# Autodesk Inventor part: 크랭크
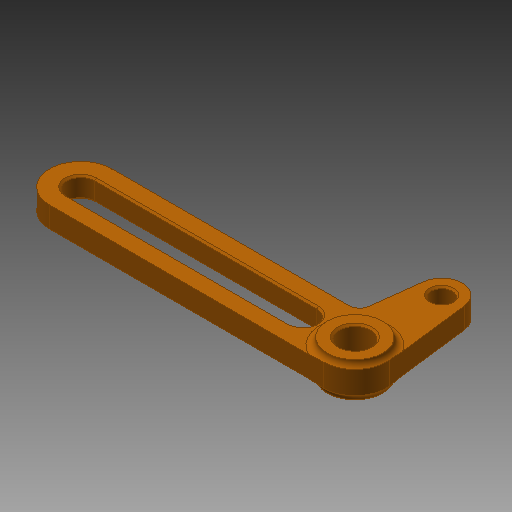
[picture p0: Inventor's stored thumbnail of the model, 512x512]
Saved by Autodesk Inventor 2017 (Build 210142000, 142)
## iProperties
Created: 2019-09
Part Number: 크랭크
Material: 알루미늄 6061
Document SubType Name: Modeling
Designer: mduedu
Density: 2.71 g/cm^3
Appearance: 주황색
Mass: 23.016 g
Surface Area: 54.7149 cm^2
Volume: 8.493 cm^3
Author: mduedu
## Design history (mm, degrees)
sketch "스케치1"
  geometry: L1 (0, 0)-(79, 0); L2 (0, 9)-(79, 9); L3 (10.637, -9)-(79, -9); L4 (0, 0)-(0, -25); L5 (-8.935, -1.08)-(-5.957, -25.72); L6 (7.659, -11.64)-(5.957, -25.72); L7 (79, -4)-(15, -4); L8 (15, 4)-(79, 4); C1 r 3 at (0, -25); A1 r 9 centre (0, 0) between (0, 9) and (-8.935, -1.08); A2 r 9 centre (79, 0) between (79, -9) and (79, 9); A3 r 6 centre (0, -25) between (-5.957, -25.72) and (5.957, -25.72); A4 r 3 centre (10.637, -12) between (10.637, -9) and (7.659, -11.64); A5 r 4 centre (79, 0) between (79, -4) and (79, 4); A6 r 4 centre (15, 0) between (15, -4) and (15, 4); 1 further point
  constraints: 16 end point, 13 point on circle, 12 tangent, 7 centre point, 5 coincident, 3 horizontal, 2 point on line, 1 equal radius, 1 perpendicular, 1 other
  dimensions: "d0" = 79 distance of L1.start L1.end; "d2" = 25 distance of L1.start L4.end; "d3" = 3 radius of A4; "d4" = 9 radius of A1; "d5" = 6 radius of A3; "d6" = 8 diameter of A5; "d7" = 64 distance of A6.centre L1.end; "d8" = 6 diameter of C1
extrude "돌출1" new body sketch "스케치1" stored distance "d9" = 6; taper "d10" = 0 deg
sketch "스케치2"
  geometry: C1 r 8 at (0, 0); 1 further point
  constraints: 1 centre point, 1 coincident
  dimensions: "d11" = 16 diameter of C1
extrude "돌출2" join sketch "스케치2" stored distance "d12" = 10; taper "d13" = 0 deg
sketch "스케치3"
  geometry: C1 r 4.5 at (0, 0); 1 further point
  constraints: 1 centre point, 1 coincident
  dimensions: "d14" = 9 diameter of C1
extrude "돌출3" cut sketch "스케치3" stored distance "d15" = 10; taper "d16" = 0 deg
fillet "모깎기1" dims "d17" = 2
chamfer "모따기1" distance "d18" = 0.5; stored, may be unused: second distance "d19" = 2, angle "d20" = 45 deg
node "솔리드1"
